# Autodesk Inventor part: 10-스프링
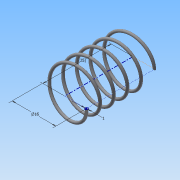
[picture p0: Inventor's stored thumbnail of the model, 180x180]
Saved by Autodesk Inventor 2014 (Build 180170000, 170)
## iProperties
Created: 2015-06
Part Number: 10-스프링
Material: 강철, 연강
Document SubType Name: Modeling
Designer: Administrator
Density: 7.86 g/cm^3
Appearance: 강철
Mass: 1.52604 g
Surface Area: 7.87202 cm^2
Volume: 0.194153 cm^3
Author: Administrator
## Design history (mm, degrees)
sketch "스케치1"
  geometry: L1 (0, 0)-(8, 0); L2 (8, 0)-(8, 14.5); L3 (8, 14.5)-(0, 14.5); L4 (0, 14.5)-(0, 0); C1 r 0.5 at (8, 0)
  constraints: 8 end point, 2 parallel, 1 centre point, 1 coincident, 1 horizontal, 1 perpendicular
  dimensions: "d0" = 14.5 distance of L3.end L1.start (derived); "d1" = 16 diameter of L1.end L4; "d2" = 1 diameter of C1
feature "코일1" sketch "스케치1" pitch "d3" = 10; turns "d5" = 5; dims "d4" = 14.5 (= d0), "d6" = 0, angle "d7" = 90 deg, angle "d8" = 90 deg, "d9" = 0, "d10" = 0
sketch "스케치2"
  geometry: L1 (15.5, -10)-(-15.5, -10); L2 (-15.5, -10)-(-15.5, 0); L3 (-15.5, 0)-(15.5, 0); L4 (15.5, 0)-(15.5, -10); L5 (-20, 24.5)-(20, 24.5); L6 (20, 24.5)-(20, 14.5); L7 (20, 14.5)-(-20, 14.5); L8 (-20, 14.5)-(-20, 24.5); 3 further points
  constraints: 16 end point, 4 parallel, 2 horizontal, 2 midpoint, 2 perpendicular, 1 coincident, 1 vertical alignment
  dimensions: "d11" = 10 distance of L3.end L1.start; "d12" = 31 distance of L1.start L1.end; "d13" = 14.5 distance between parallel lines of L3 L7 (= d0); "d14" = 10 distance of L5.end L6.end; "d15" = 40 distance of L5.start L5.end
extrude "돌출1" cut sketch "스케치2" stored distance "d16" = 0; taper "d17" = 0 deg
node "솔리드1"
